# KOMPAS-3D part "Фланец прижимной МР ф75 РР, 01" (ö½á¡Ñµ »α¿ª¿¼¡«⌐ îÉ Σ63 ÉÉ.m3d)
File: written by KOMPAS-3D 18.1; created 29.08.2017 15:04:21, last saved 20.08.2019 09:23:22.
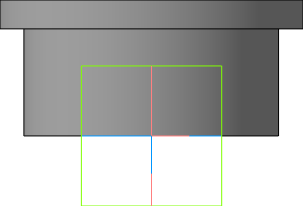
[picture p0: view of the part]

Document properties: Автор: Милов; Организация: Милов; Полное имя файла: D:\1 ПКИ 3D\Полипропиленовые фитинги, трубы\Разборные муфты\Фланец прижимной МР ф63 РР.m3d

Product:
- Part/product: Фланец прижимной МР ф75 РР  | designation 01
    Материал: Полипропилен  ГОСТ 26996-86 (density 900 kg/m3)
    Масса: 0.119147
- Part/product: Фланец прижимной МР ф63 РР
    Материал: Полипропилен  ГОСТ 26996-86 (density 900 kg/m3)
    Масса: 0.06666

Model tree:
1. Эскиз:1
2. Операция вращения:1  (labels: Полипропилен  ГОСТ 26996-86)
     Угол 1 = 360
3. Масштабирование:1  (labels: Полипропилен  ГОСТ 26996-86; 1729499839-394-0-0|0)
     Коэффициент = 1.21359

Expressions: 75/2; 89/2; 50.4/2; 61.8/2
